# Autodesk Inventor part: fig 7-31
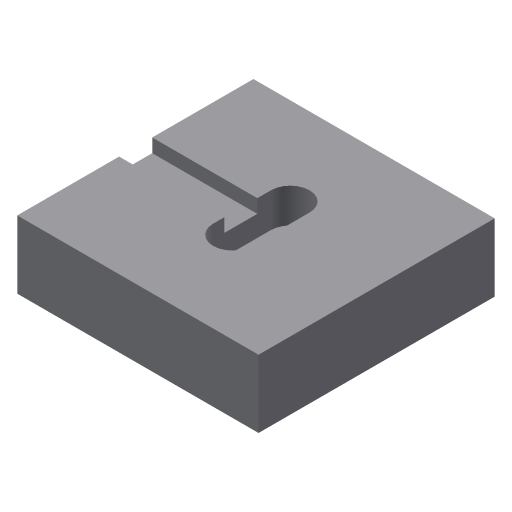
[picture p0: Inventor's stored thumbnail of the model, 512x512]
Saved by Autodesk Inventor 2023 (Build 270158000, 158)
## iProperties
Created: 2004-05
Part Number: fig 7-31
Document SubType Name: Modeling
Designer: CADCIM Technologies
Manufacturer: Standard
Standards Organization: Custom
Density: 1 g/cm^3
Material: Generic
Appearance: Default
Author: CADCIM Technologies
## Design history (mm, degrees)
sketch "Sketch1"
  geometry: L1 (-30.233, -25.517)-(22.302, -25.517); L2 (22.302, -25.517)-(22.302, 25.904); L3 (22.302, 25.904)-(-30.233, 25.904); L4 (-30.233, 25.904)-(-30.233, -25.517)
  constraints: 8 end point, 2 parallel, 1 horizontal, 1 perpendicular
extrude "Extrusion1" new body sketch "Sketch1" distance "d0" = 14.75; taper "d1" = 0 deg
sketch "Sketch2"
  geometry: L1 (1.047, -5.75)-(1.047, 6.846); L2 (-7.35, 6.845)-(-7.35, -5.75); A1 r 4.198 centre (-3.152, 6.846) between (1.047, 6.846) and (-7.35, 6.845); A2 r 4.198 centre (-3.152, -5.75) between (-7.35, -5.75) and (1.047, -5.75)
  constraints: 4 end point, 4 point on circle, 4 tangent, 2 centre point, 1 parallel
extrude "Extrusion2" cut sketch "Sketch2" distance "d2" = 7.5; taper "d3" = 0 deg
sketch "Sketch3"
  geometry: L1 (-7.5, 0)-(-7.5, 12.595) reference; L2 (-7.5, 0)-(0, 0) reference; L3 (-7.5, 2.416)-(-4.537, 2.416); L4 (-4.537, 2.416)-(-4.537, 9.616); L5 (-4.537, 9.616)-(-7.5, 9.616)
  constraints: 6 end point, 2 perpendicular, 2 point on line, 1 parallel
extrude "Extrusion3" cut sketch "Sketch3" extent not by distance; stored distance "d4" = 6.75; taper "d5" = 0 deg
body "Solid1"
